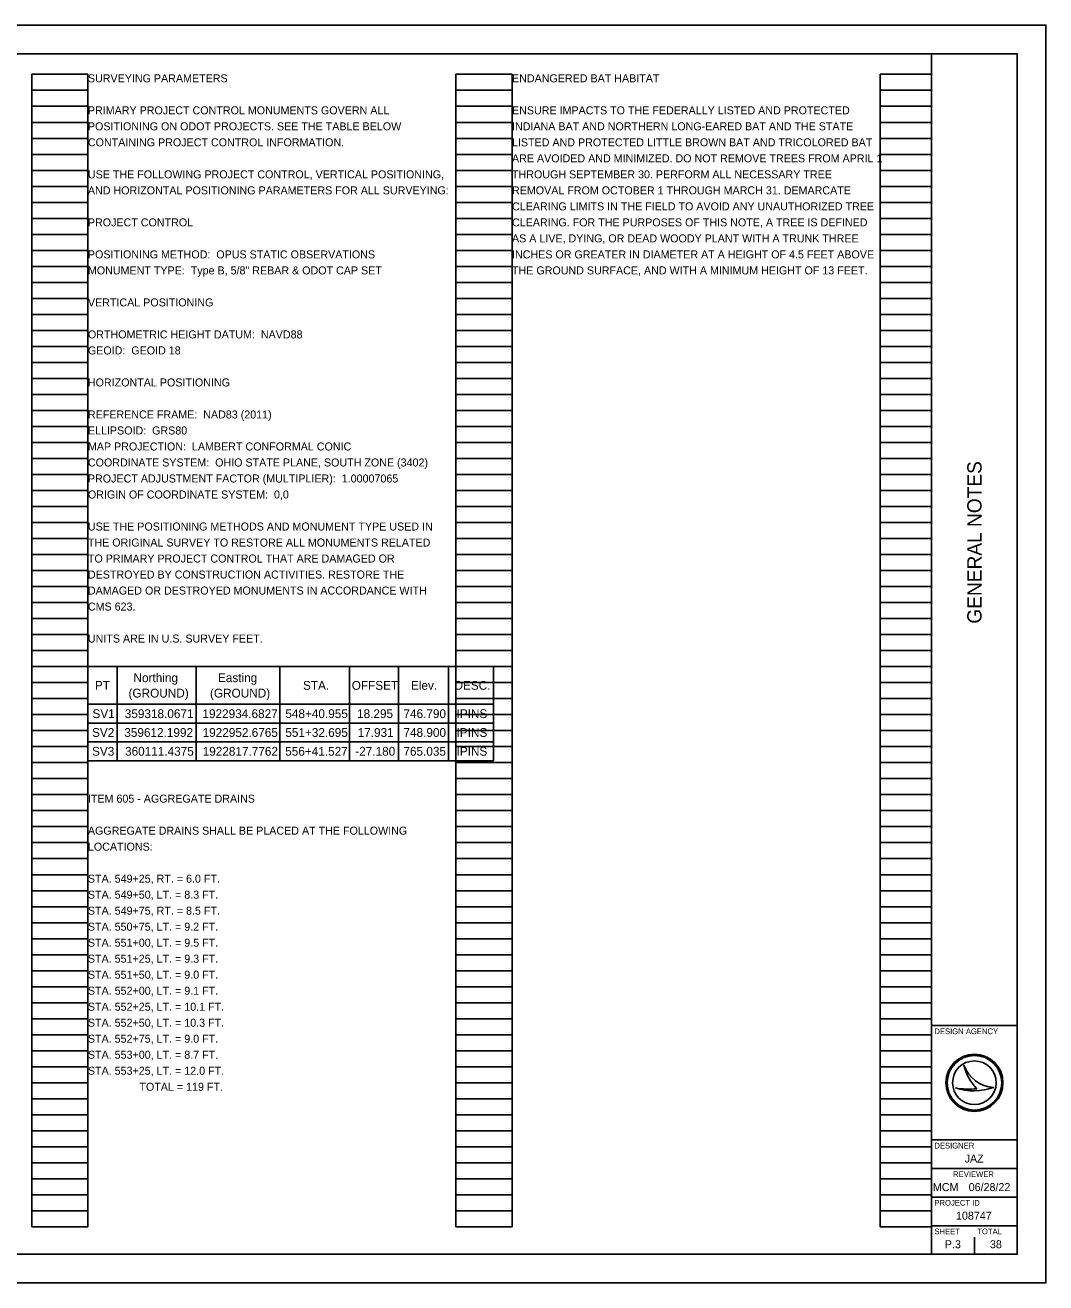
# Model space of a CAD drawing. Extents: x 0 to 34, y 0 to 22.
# Drawn here: x 16.14 to 34, y 0 to 22 of the extents above; entities that cross this region are included whole.
import ezdxf

# ---------------------------------------------------------------- set-up
doc = ezdxf.new("R2010")
doc.units = 0
for name, color, linetype in [('SH_Border', 7, 'Continuous'), ('SH_Cut_Line', 7, 'Continuous'), ('SH_Data', 7, 'Continuous'), ('SH_Text', 7, 'Continuous')]:
    doc.layers.add(name, color=color, linetype=linetype)

msp = doc.modelspace()

# ---------------------------------------------------------------- linework, layer by layer
at = {"layer": 'SH_Border'}
for p, q in [((32, 0.5), (32, 21.5)), ((32, 4.5), (33.5, 4.5)), ((32, 2.5), (33.5, 2.5)), ((32, 2), (33.5, 2)), ((32, 1.5), (33.5, 1.5)), ((32, 1), (33.5, 1))]:
    msp.add_line(p, q, dxfattribs=at)
msp.add_lwpolyline([(1.5, 21.5), (33.5, 21.5), (33.5, 0.5), (1.5, 0.5)], close=True, dxfattribs=at)
at = {"layer": 'SH_Cut_Line'}
msp.add_lwpolyline([(0, 0), (34, 0), (34, 22), (0, 22)], close=True, dxfattribs=at)
at = {"layer": 'SH_Data'}
for p, q in [((16.26, 0.98), (16.26, 21.14)), ((16.26, 21.14), (17.24, 21.14)), ((17.24, 0.98), (17.24, 21.14)), ((23.68, 0.98), (23.68, 21.14)), ((23.68, 21.14), (24.66, 21.14)), ((24.66, 0.98), (24.66, 21.14)), ((31.1, 0.98), (31.1, 21.14)), ((31.1, 21.14), (32, 21.14)), ((32, 0.98), (32, 21.14)), ((16.26, 20.86), (17.24, 20.86)), ((23.68, 20.86), (24.66, 20.86)), ((31.1, 20.86), (32, 20.86)), ((16.26, 20.58), (17.24, 20.58)), ((23.68, 20.58), (24.66, 20.58)), ((31.1, 20.58), (32, 20.58)), ((16.26, 20.3), (17.24, 20.3)), ((23.68, 20.3), (24.66, 20.3)), ((31.1, 20.3), (32, 20.3)), ((16.26, 20.02), (17.24, 20.02)), ((23.68, 20.02), (24.66, 20.02)), ((31.1, 20.02), (32, 20.02)), ((16.26, 19.74), (17.24, 19.74)), ((23.68, 19.74), (24.66, 19.74)), ((31.1, 19.74), (32, 19.74)), ((16.26, 19.46), (17.24, 19.46)), ((23.68, 19.46), (24.66, 19.46)), ((31.1, 19.46), (32, 19.46)), ((16.26, 19.18), (17.24, 19.18)), ((23.68, 19.18), (24.66, 19.18)), ((31.1, 19.18), (32, 19.18)), ((16.26, 18.9), (17.24, 18.9)), ((23.68, 18.9), (24.66, 18.9)), ((31.1, 18.9), (32, 18.9)), ((16.26, 18.62), (17.24, 18.62)), ((23.68, 18.62), (24.66, 18.62)), ((31.1, 18.62), (32, 18.62)), ((16.26, 18.34), (17.24, 18.34)), ((23.68, 18.34), (24.66, 18.34)), ((31.1, 18.34), (32, 18.34)), ((16.26, 18.06), (17.24, 18.06)), ((23.68, 18.06), (24.66, 18.06)), ((31.1, 18.06), (32, 18.06)), ((16.26, 17.78), (17.24, 17.78)), ((23.68, 17.78), (24.66, 17.78)), ((31.1, 17.78), (32, 17.78)), ((16.26, 17.5), (17.24, 17.5)), ((23.68, 17.5), (24.66, 17.5)), ((31.1, 17.5), (32, 17.5)), ((16.26, 17.22), (17.24, 17.22)), ((23.68, 17.22), (24.66, 17.22)), ((31.1, 17.22), (32, 17.22)), ((16.26, 16.94), (17.24, 16.94)), ((23.68, 16.94), (24.66, 16.94)), ((31.1, 16.94), (32, 16.94)), ((16.26, 16.66), (17.24, 16.66)), ((23.68, 16.66), (24.66, 16.66)), ((31.1, 16.66), (32, 16.66)), ((16.26, 16.38), (17.24, 16.38)), ((23.68, 16.38), (24.66, 16.38)), ((31.1, 16.38), (32, 16.38)), ((16.26, 16.1), (17.24, 16.1)), ((23.68, 16.1), (24.66, 16.1)), ((31.1, 16.1), (32, 16.1)), ((16.26, 15.82), (17.24, 15.82)), ((23.68, 15.82), (24.66, 15.82)), ((31.1, 15.82), (32, 15.82)), ((16.26, 15.54), (17.24, 15.54)), ((23.68, 15.54), (24.66, 15.54)), ((31.1, 15.54), (32, 15.54)), ((16.26, 15.26), (17.24, 15.26)), ((23.68, 15.26), (24.66, 15.26)), ((31.1, 15.26), (32, 15.26)), ((16.26, 14.98), (17.24, 14.98)), ((23.68, 14.98), (24.66, 14.98)), ((31.1, 14.98), (32, 14.98)), ((16.26, 14.7), (17.24, 14.7)), ((23.68, 14.7), (24.66, 14.7)), ((31.1, 14.7), (32, 14.7)), ((16.26, 14.42), (17.24, 14.42)), ((23.68, 14.42), (24.66, 14.42)), ((31.1, 14.42), (32, 14.42)), ((16.26, 14.14), (17.24, 14.14)), ((23.68, 14.14), (24.66, 14.14)), ((31.1, 14.14), (32, 14.14)), ((16.26, 13.86), (17.24, 13.86)), ((23.68, 13.86), (24.66, 13.86)), ((31.1, 13.86), (32, 13.86)), ((16.26, 13.58), (17.24, 13.58)), ((23.68, 13.58), (24.66, 13.58)), ((31.1, 13.58), (32, 13.58)), ((16.26, 13.3), (17.24, 13.3)), ((23.68, 13.3), (24.66, 13.3)), ((31.1, 13.3), (32, 13.3)), ((16.26, 13.02), (17.24, 13.02)), ((23.68, 13.02), (24.66, 13.02)), ((31.1, 13.02), (32, 13.02)), ((16.26, 12.74), (17.24, 12.74)), ((23.68, 12.74), (24.66, 12.74)), ((31.1, 12.74), (32, 12.74)), ((16.26, 12.46), (17.24, 12.46)), ((23.68, 12.46), (24.66, 12.46)), ((31.1, 12.46), (32, 12.46)), ((16.26, 12.18), (17.24, 12.18)), ((23.68, 12.18), (24.66, 12.18)), ((31.1, 12.18), (32, 12.18)), ((16.26, 11.9), (17.24, 11.9)), ((23.68, 11.9), (24.66, 11.9)), ((31.1, 11.9), (32, 11.9)), ((16.26, 11.62), (17.24, 11.62)), ((23.68, 11.62), (24.66, 11.62)), ((31.1, 11.62), (32, 11.62)), ((16.26, 11.34), (17.24, 11.34)), ((23.68, 11.34), (24.66, 11.34)), ((31.1, 11.34), (32, 11.34)), ((16.26, 11.06), (17.24, 11.06)), ((23.68, 11.06), (24.66, 11.06)), ((31.1, 11.06), (32, 11.06)), ((16.26, 10.78), (17.24, 10.78)), ((23.68, 10.78), (24.66, 10.78)), ((31.1, 10.78), (32, 10.78)), ((16.26, 10.5), (17.24, 10.5)), ((23.68, 10.5), (24.66, 10.5)), ((31.1, 10.5), (32, 10.5)), ((16.26, 10.22), (17.24, 10.22)), ((23.68, 10.22), (24.66, 10.22)), ((31.1, 10.22), (32, 10.22)), ((16.26, 9.94), (17.24, 9.94)), ((23.68, 9.94), (24.66, 9.94)), ((31.1, 9.94), (32, 9.94)), ((16.26, 9.66), (17.24, 9.66)), ((23.68, 9.66), (24.66, 9.66)), ((31.1, 9.66), (32, 9.66)), ((16.26, 9.38), (17.24, 9.38)), ((23.68, 9.38), (24.66, 9.38)), ((31.1, 9.38), (32, 9.38)), ((16.26, 9.1), (17.24, 9.1)), ((23.68, 9.1), (24.66, 9.1)), ((31.1, 9.1), (32, 9.1)), ((16.26, 8.82), (17.24, 8.82)), ((23.68, 8.82), (24.66, 8.82)), ((31.1, 8.82), (32, 8.82)), ((16.26, 8.54), (17.24, 8.54)), ((23.68, 8.54), (24.66, 8.54)), ((31.1, 8.54), (32, 8.54)), ((16.26, 8.26), (17.24, 8.26)), ((23.68, 8.26), (24.66, 8.26)), ((31.1, 8.26), (32, 8.26)), ((16.26, 7.98), (17.24, 7.98)), ((23.68, 7.98), (24.66, 7.98)), ((31.1, 7.98), (32, 7.98)), ((16.26, 7.7), (17.24, 7.7)), ((23.68, 7.7), (24.66, 7.7)), ((31.1, 7.7), (32, 7.7)), ((16.26, 7.42), (17.24, 7.42)), ((23.68, 7.42), (24.66, 7.42)), ((31.1, 7.42), (32, 7.42)), ((16.26, 7.14), (17.24, 7.14)), ((23.68, 7.14), (24.66, 7.14)), ((31.1, 7.14), (32, 7.14)), ((16.26, 6.86), (17.24, 6.86)), ((23.68, 6.86), (24.66, 6.86)), ((31.1, 6.86), (32, 6.86)), ((16.26, 6.58), (17.24, 6.58)), ((23.68, 6.58), (24.66, 6.58)), ((31.1, 6.58), (32, 6.58)), ((16.26, 6.3), (17.24, 6.3)), ((23.68, 6.3), (24.66, 6.3)), ((31.1, 6.3), (32, 6.3)), ((16.26, 6.02), (17.24, 6.02)), ((23.68, 6.02), (24.66, 6.02)), ((31.1, 6.02), (32, 6.02)), ((16.26, 5.74), (17.24, 5.74)), ((23.68, 5.74), (24.66, 5.74)), ((31.1, 5.74), (32, 5.74)), ((16.26, 5.46), (17.24, 5.46)), ((23.68, 5.46), (24.66, 5.46)), ((31.1, 5.46), (32, 5.46)), ((16.26, 5.18), (17.24, 5.18)), ((23.68, 5.18), (24.66, 5.18)), ((31.1, 5.18), (32, 5.18)), ((16.26, 4.9), (17.24, 4.9)), ((23.68, 4.9), (24.66, 4.9)), ((31.1, 4.9), (32, 4.9)), ((16.26, 4.62), (17.24, 4.62)), ((23.68, 4.62), (24.66, 4.62)), ((31.1, 4.62), (32, 4.62)), ((16.26, 4.34), (17.24, 4.34)), ((23.68, 4.34), (24.66, 4.34)), ((31.1, 4.34), (32, 4.34)), ((16.26, 4.06), (17.24, 4.06)), ((23.68, 4.06), (24.66, 4.06)), ((31.1, 4.06), (32, 4.06)), ((16.26, 3.78), (17.24, 3.78)), ((23.68, 3.78), (24.66, 3.78)), ((31.1, 3.78), (32, 3.78)), ((32.567, 3.81), (32.567, 3.81)), ((16.26, 3.5), (17.24, 3.5)), ((23.68, 3.5), (24.66, 3.5)), ((31.1, 3.5), (32, 3.5)), ((32.417, 3.41), (32.417, 3.41)), ((32.75, 3.5), (32.75, 3.5)), ((33.087, 3.419), (33.087, 3.419)), ((16.26, 3.22), (17.24, 3.22)), ((23.68, 3.22), (24.66, 3.22)), ((31.1, 3.22), (32, 3.22)), ((16.26, 2.94), (17.24, 2.94)), ((23.68, 2.94), (24.66, 2.94)), ((31.1, 2.94), (32, 2.94)), ((16.26, 2.66), (17.24, 2.66)), ((23.68, 2.66), (24.66, 2.66)), ((31.1, 2.66), (32, 2.66)), ((16.26, 2.38), (17.24, 2.38)), ((23.68, 2.38), (24.66, 2.38)), ((31.1, 2.38), (32, 2.38)), ((16.26, 2.1), (17.24, 2.1)), ((23.68, 2.1), (24.66, 2.1)), ((31.1, 2.1), (32, 2.1)), ((16.26, 1.82), (17.24, 1.82)), ((23.68, 1.82), (24.66, 1.82)), ((31.1, 1.82), (32, 1.82)), ((16.26, 1.54), (17.24, 1.54)), ((23.68, 1.54), (24.66, 1.54)), ((31.1, 1.54), (32, 1.54)), ((16.26, 1.26), (17.24, 1.26)), ((23.68, 1.26), (24.66, 1.26)), ((31.1, 1.26), (32, 1.26)), ((16.26, 0.98), (17.24, 0.98)), ((23.68, 0.98), (24.66, 0.98)), ((31.1, 0.98), (32, 0.98)), ((32.375, 0.675), (32.375, 0.675)), ((32.75, 0.5), (32.75, 0.8))]:
    msp.add_line(p, q, dxfattribs=at)
for radius in [0.5, 0.477, 0.477, 0.382]:
    msp.add_circle((32.75, 3.5), radius, dxfattribs=at)
for centre, radius, start, end in [((33.116, 3.998), 0.58, 198.9257, 198.9319), ((33.347, 3.97), 0.796, 191.6379, 191.6421), ((33.116, 3.998), 0.58, 198.9319, 267.1657), ((33.347, 3.97), 0.796, 191.6421, 226.0947), ((32.739, 4.37), 1.013, 251.4576, 290.0832), ((32.648, 4.654), 1.266, 259.4964, 259.4995), ((32.739, 4.37), 1.013, 251.4527, 251.4576), ((32.648, 4.654), 1.266, 259.4995, 276.6672)]:
    msp.add_arc(centre, radius, start, end, dxfattribs=at)
at = {"layer": 'SH_Text'}
for p, q in [((17.24, 10.78), (24.339, 10.78)), ((17.24, 10.78), (17.24, 9.133)), ((17.751, 10.78), (17.751, 9.133)), ((19.134, 10.78), (19.134, 9.133)), ((20.6, 10.78), (20.6, 9.133)), ((21.819, 10.78), (21.819, 9.133)), ((22.675, 10.78), (22.675, 9.133)), ((23.548, 10.78), (23.548, 9.133)), ((24.339, 10.78), (24.339, 9.133)), ((17.24, 10.121), (24.339, 10.121)), ((17.24, 9.792), (24.339, 9.792)), ((17.24, 9.462), (24.339, 9.462)), ((17.24, 9.133), (24.339, 9.133))]:
    msp.add_line(p, q, dxfattribs=at)

# ---------------------------------------------------------------- texts
at = {"layer": 'SH_Data'}
msp.add_text('GENERAL NOTES', height=0.25, rotation=90, dxfattribs=at).set_placement((32.875, 11.531))
for s, height, p in [('DESIGN AGENCY', 0.1, (32.05, 4.35)), ('DESIGNER', 0.1, (32.05, 2.35)), ('JAZ', 0.14, (32.579, 2.105)), ('REVIEWER', 0.1, (32.378, 1.85)), ('MCM', 0.14, (32.024, 1.605)), ('06/28/22', 0.14, (32.65, 1.605)), ('PROJECT ID', 0.1, (32.05, 1.35)), ('108747', 0.14, (32.428, 1.105)), ('SHEET', 0.1, (32.05, 0.85)), ('TOTAL', 0.1, (32.8, 0.85)), ('P.3', 0.14, (32.233, 0.605)), ('38', 0.14, (33.021, 0.605))]:
    msp.add_text(s, height=height, dxfattribs=at).set_placement(p)
at = {"layer": 'SH_Text'}
for s, height, p in [('SURVEYING PARAMETERS', 0.14, (17.24, 21)), ('ENDANGERED BAT HABITAT', 0.14, (24.66, 21)), ('PRIMARY PROJECT CONTROL MONUMENTS GOVERN ALL', 0.14, (17.24, 20.44)), ('ENSURE IMPACTS TO THE FEDERALLY LISTED AND PROTECTED', 0.14, (24.66, 20.44)), ('POSITIONING ON ODOT PROJECTS. SEE THE TABLE BELOW', 0.14, (17.24, 20.16)), ('INDIANA BAT AND NORTHERN LONG-EARED BAT AND THE STATE', 0.14, (24.66, 20.16)), ('CONTAINING PROJECT CONTROL INFORMATION.', 0.14, (17.24, 19.88)), ('LISTED AND PROTECTED LITTLE BROWN BAT AND TRICOLORED BAT', 0.14, (24.66, 19.88)), ('ARE AVOIDED AND MINIMIZED. DO NOT REMOVE TREES FROM APRIL 1', 0.14, (24.66, 19.6)), ('USE THE FOLLOWING PROJECT CONTROL, VERTICAL POSITIONING,', 0.14, (17.24, 19.32)), ('THROUGH SEPTEMBER 30. PERFORM ALL NECESSARY TREE', 0.14, (24.66, 19.32)), ('AND HORIZONTAL POSITIONING PARAMETERS FOR ALL SURVEYING:', 0.14, (17.24, 19.04)), ('REMOVAL FROM OCTOBER 1 THROUGH MARCH 31. DEMARCATE', 0.14, (24.66, 19.04)), ('CLEARING LIMITS IN THE FIELD TO AVOID ANY UNAUTHORIZED TREE', 0.14, (24.66, 18.76)), ('PROJECT CONTROL', 0.14, (17.24, 18.48)), ('CLEARING. FOR THE PURPOSES OF THIS NOTE, A TREE IS DEFINED', 0.14, (24.66, 18.48)), ('AS A LIVE, DYING, OR DEAD WOODY PLANT WITH A TRUNK THREE', 0.14, (24.66, 18.2)), ('POSITIONING METHOD:  OPUS STATIC OBSERVATIONS', 0.14, (17.24, 17.92)), ('INCHES OR GREATER IN DIAMETER AT A HEIGHT OF 4.5 FEET ABOVE', 0.14, (24.66, 17.92)), ('MONUMENT TYPE:  Type B, 5/8" REBAR & ODOT CAP SET', 0.14, (17.24, 17.64)), ('THE GROUND SURFACE, AND WITH A MINIMUM HEIGHT OF 13 FEET.', 0.14, (24.66, 17.64)), ('VERTICAL POSITIONING', 0.14, (17.24, 17.08)), ('ORTHOMETRIC HEIGHT DATUM:  NAVD88', 0.14, (17.24, 16.52)), ('GEOID:  GEOID 18', 0.14, (17.24, 16.24)), ('HORIZONTAL POSITIONING', 0.14, (17.24, 15.68)), ('REFERENCE FRAME:  NAD83 (2011)', 0.14, (17.24, 15.12)), ('ELLIPSOID:  GRS80', 0.14, (17.24, 14.84)), ('MAP PROJECTION:  LAMBERT CONFORMAL CONIC', 0.14, (17.24, 14.56)), ('COORDINATE SYSTEM:  OHIO STATE PLANE, SOUTH ZONE (3402)', 0.14, (17.24, 14.28)), ('PROJECT ADJUSTMENT FACTOR (MULTIPLIER):  1.00007065', 0.14, (17.24, 14)), ('ORIGIN OF COORDINATE SYSTEM:  0,0', 0.14, (17.24, 13.72)), ('USE THE POSITIONING METHODS AND MONUMENT TYPE USED IN', 0.14, (17.24, 13.16)), ('THE ORIGINAL SURVEY TO RESTORE ALL MONUMENTS RELATED', 0.14, (17.24, 12.88)), ('TO PRIMARY PROJECT CONTROL THAT ARE DAMAGED OR', 0.14, (17.24, 12.6)), ('DESTROYED BY CONSTRUCTION ACTIVITIES. RESTORE THE', 0.14, (17.24, 12.32)), ('DAMAGED OR DESTROYED MONUMENTS IN ACCORDANCE WITH', 0.14, (17.24, 12.04)), ('CMS 623.', 0.14, (17.24, 11.76)), ('UNITS ARE IN U.S. SURVEY FEET.', 0.14, (17.24, 11.2)), ('Northing', 0.154, (18.038, 10.508)), ('Easting', 0.154, (19.516, 10.508)), ('PT', 0.154, (17.362, 10.374)), ('(GROUND)', 0.154, (17.951, 10.239)), ('(GROUND)', 0.154, (19.376, 10.239)), ('STA.', 0.154, (21.003, 10.374)), ('OFFSET', 0.154, (21.856, 10.374)), ('Elev.', 0.154, (22.892, 10.374)), ('DESC.', 0.154, (23.654, 10.374)), ('SV1', 0.154, (17.32, 9.879)), ('359318.0671', 0.154, (17.885, 9.879)), ('1922934.6827', 0.154, (19.244, 9.879)), ('548+40.955', 0.154, (20.694, 9.879)), ('18.295', 0.154, (21.949, 9.879)), ('746.790', 0.154, (22.761, 9.879)), ('IPINS', 0.154, (23.69, 9.879)), ('SV2', 0.154, (17.312, 9.55)), ('359612.1992', 0.154, (17.877, 9.55)), ('1922952.6765', 0.154, (19.247, 9.55)), ('551+32.695', 0.154, (20.694, 9.55)), ('17.931', 0.154, (21.959, 9.55)), ('748.900', 0.154, (22.761, 9.55)), ('IPINS', 0.154, (23.69, 9.55)), ('SV3', 0.154, (17.312, 9.221)), ('360111.4375', 0.154, (17.89, 9.221)), ('1922817.7762', 0.154, (19.248, 9.221)), ('556+41.527', 0.154, (20.692, 9.221)), ('-27.180', 0.154, (21.918, 9.221)), ('765.035', 0.154, (22.76, 9.221)), ('IPINS', 0.154, (23.69, 9.221)), ('ITEM 605 - AGGREGATE DRAINS', 0.14, (17.24, 8.4)), ('AGGREGATE DRAINS SHALL BE PLACED AT THE FOLLOWING', 0.14, (17.24, 7.84)), ('LOCATIONS:', 0.14, (17.24, 7.56)), ('STA. 549+25, RT. = 6.0 FT.', 0.14, (17.24, 7)), ('STA. 549+50, LT. = 8.3 FT.', 0.14, (17.24, 6.72)), ('STA. 549+75, RT. = 8.5 FT.', 0.14, (17.24, 6.44)), ('STA. 550+75, LT. = 9.2 FT.', 0.14, (17.24, 6.16)), ('STA. 551+00, LT. = 9.5 FT.', 0.14, (17.24, 5.88)), ('STA. 551+25, LT. = 9.3 FT.', 0.14, (17.24, 5.6)), ('STA. 551+50, LT. = 9.0 FT.', 0.14, (17.24, 5.32)), ('STA. 552+00, LT. = 9.1 FT.', 0.14, (17.24, 5.04)), ('STA. 552+25, LT. = 10.1 FT.', 0.14, (17.24, 4.76)), ('STA. 552+50, LT. = 10.3 FT.', 0.14, (17.24, 4.48)), ('STA. 552+75, LT. = 9.0 FT.', 0.14, (17.24, 4.2)), ('STA. 553+00, LT. = 8.7 FT.', 0.14, (17.24, 3.92)), ('STA. 553+25, LT. = 12.0 FT.', 0.14, (17.24, 3.64)), ('TOTAL = 119 FT.', 0.14, (18.141, 3.36))]:
    msp.add_text(s, height=height, dxfattribs=at).set_placement(p)

doc.saveas('drawing.dxf')
